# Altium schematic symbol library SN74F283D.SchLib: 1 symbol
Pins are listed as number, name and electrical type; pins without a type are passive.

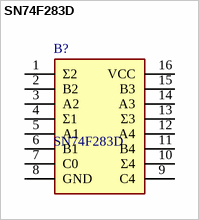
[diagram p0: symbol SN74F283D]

## SN74F283D
designator B?
4-BITBIN FULL ADDER; Manufacturer_Name: Texas Instruments; Geometry.Height: 1.75mm
footprint SOIC127P600X175-16N
pins: 1 Σ2, 2 B2, 3 A2, 4 Σ1, 5 A1, 6 B1, 7 C0, 8 GND, 9 C4, 10 Σ4, 11 B4, 12 A4, 13 Σ3, 14 A3, 15 B3, 16 VCC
